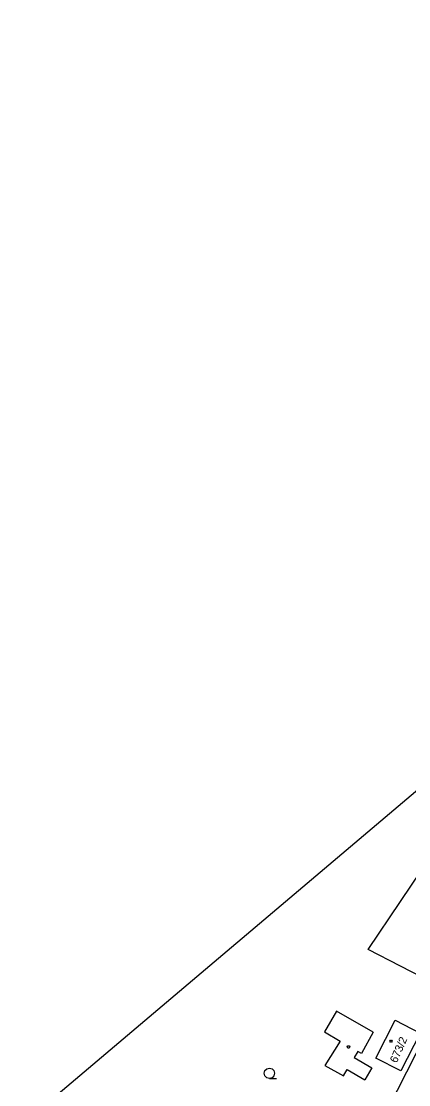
# Model space of a CAD drawing. Extents: x -759699 to -757730, y -1172308 to -1170857.
# Drawn here: x -758511 to -758455.8, y -1171215.9 to -1171064.4 of the extents above; entities that cross this region are included whole.
import ezdxf

# ---------------------------------------------------------------- set-up
doc = ezdxf.new("R2010")
doc.units = 0
for name, color, linetype in [('Vrstva 1', 7, 'Continuous'), ('Vrstva 11', 7, 'Continuous'), ('Vrstva 12', 7, 'Continuous'), ('Vrstva 2', 7, 'Continuous'), ('Vrstva 3', 7, 'Continuous'), ('Vrstva 4', 7, 'Continuous'), ('Vrstva 5', 7, 'Continuous')]:
    doc.layers.add(name, color=color, linetype=linetype)

msp = doc.modelspace()

# ---------------------------------------------------------------- linework, layer by layer
at = {"layer": 'Vrstva 1'}
for p, q in [((-758461.59, -1171196.64), (-758436.69, -1171159.51)), ((-758439.16, -1171208.23), (-758461.59, -1171196.64)), ((-758461.59, -1171196.64), (-758461.59, -1171196.64)), ((-758460.51, -1171212.12), (-758457.73, -1171206.7)), ((-758457.73, -1171206.7), (-758454.16, -1171208.54)), ((-758457.73, -1171206.7), (-758457.73, -1171206.7)), ((-758454.16, -1171208.54), (-758456.92, -1171213.92)), ((-758453.47, -1171208.89), (-758458.92, -1171219.58)), ((-758456.92, -1171213.92), (-758460.51, -1171212.12))]:
    msp.add_line(p, q, dxfattribs=at)
at = {"layer": 'Vrstva 11'}
msp.add_line((-758128.76, -1170897.97), (-758510.97, -1171221.67), dxfattribs=at)
at = {"layer": 'Vrstva 12'}
for p, q in [((-758460.51, -1171212.12), (-758457.73, -1171206.7)), ((-758457.73, -1171206.7), (-758454.16, -1171208.54)), ((-758454.16, -1171208.54), (-758456.92, -1171213.92)), ((-758456.92, -1171213.92), (-758460.51, -1171212.12))]:
    msp.add_line(p, q, dxfattribs=at)
at = {"layer": 'Vrstva 3'}
msp.add_lwpolyline([(-758475.63, -1171214.99), (-758476.01, -1171214.89), (-758476.28, -1171214.62), (-758476.38, -1171214.25), (-758476.28, -1171213.88), (-758476.01, -1171213.61), (-758475.64, -1171213.51), (-758475.27, -1171213.61), (-758475, -1171213.88), (-758474.9, -1171214.26), (-758475, -1171214.64), (-758475.27, -1171214.91), (-758475.65, -1171215.01), (-758474.65, -1171215.01)], dxfattribs=at)
at = {"layer": 'Vrstva 4'}
for p, q in [((-758466.1, -1171205.39), (-758467.81, -1171208.37)), ((-758460.85, -1171208.39), (-758466.1, -1171205.39)), ((-758467.81, -1171208.37), (-758465.56, -1171209.69)), ((-758460.85, -1171208.39), (-758462.53, -1171211.45)), ((-758465.56, -1171209.69), (-758467.74, -1171213.15)), ((-758463.05, -1171211.15), (-758463.57, -1171212.03)), ((-758462.53, -1171211.45), (-758463.05, -1171211.15)), ((-758467.74, -1171213.15), (-758465.11, -1171214.64)), ((-758463.57, -1171212.03), (-758461.07, -1171213.5)), ((-758465.11, -1171214.64), (-758464.58, -1171213.74)), ((-758464.58, -1171213.74), (-758462.08, -1171215.21)), ((-758461.07, -1171213.5), (-758462.08, -1171215.21))]:
    msp.add_line(p, q, dxfattribs=at)
at = {"layer": 'Vrstva 5'}
for points in [[(-758458.24, -1171209.54), (-758458.15, -1171209.69), (-758458.24, -1171209.84), (-758458.42, -1171209.84), (-758458.51, -1171209.69), (-758458.42, -1171209.54)], [(-758464.29, -1171210.36), (-758464.2, -1171210.51), (-758464.29, -1171210.66), (-758464.47, -1171210.66), (-758464.56, -1171210.51), (-758464.47, -1171210.36)]]:
    msp.add_lwpolyline(points, close=True, dxfattribs=at)

# ---------------------------------------------------------------- texts
at = {"layer": 'Vrstva 2'}
msp.add_text('673/2', height=1.14, rotation=66.40581, dxfattribs=at).set_placement((-758457.514, -1171212.874))

doc.saveas('drawing.dxf')
